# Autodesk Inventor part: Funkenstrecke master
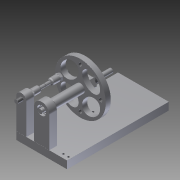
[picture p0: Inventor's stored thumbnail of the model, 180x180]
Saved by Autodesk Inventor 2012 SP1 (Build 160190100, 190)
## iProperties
Created: 2012-10
Part Number: Funkenstrecke master
Material: Default
Document SubType Name: Modeling
Designer: Dominic Mähling
Density: 1 g/cm^3
Author: Dominic Mähling
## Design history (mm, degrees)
sketch "Skizze1"
  geometry: L1 (100, -200)-(-100, -200); L2 (-100, -200)-(-100, 200); L3 (-100, 200)-(100, 200); L4 (100, 200)-(100, -200); 3 further points
  constraints: 8 end point, 2 midpoint, 2 parallel, 1 horizontal, 1 horizontal alignment, 1 perpendicular, 1 vertical alignment
  dimensions: "d0" = 200 distance of L2.end L3.end; "d1" = 400 distance of L1.end L2.end
extrude "Extrusion1" new body sketch "Skizze1" distance "d2" = 30; taper "d3" = 0 deg
sketch "Skizze3"
  geometry: L1 (200, 30)-(0, 30) reference; L2 (0, 30)-(0, 150); L3 (40, 30)-(40, 150); L4 (70, 30)-(70, 150); L5 (130, 30)-(130, 150); A1 r 20 centre (20, 150) between (40, 150) and (0, 150); A2 r 30 centre (100, 150) between (130, 150) and (70, 150); 2 further points
  constraints: 8 end point, 4 point on circle, 4 tangent, 3 parallel, 3 point on line, 2 centre point, 1 horizontal alignment, 1 midpoint, 1 perpendicular, 1 vertical alignment
  dimensions: "d4" = 120 distance of L1.end L2.end; "d6" = 40 distance between parallel lines of L2 L3; "d7" = 60 distance between parallel lines of L5 L4
extrude "Extrusion2" new body sketch "Skizze3" distance "d8" = 30; taper "d9" = 0 deg
extrude "Extrusion3" new body sketch "Skizze3" distance "d10" = 30; taper "d11" = 0 deg
sketch "Skizze4"
  geometry: A1 r 30 centre (100, 150) between (130, 150) and (70, 150) reference; 2 further points
  constraints: 1 coincident
hole "Bohrung1" sketch "Skizze4" at (100, 150) diameter "d12" = 30; stored, may be unused: countersink angle "d16" = 90 deg, drill point angle "d18" = 118 deg; dims "d13" = 6, "d14" = 35, "d15" = 10, "d17" = 8
sketch "Skizze5"
  geometry: A1 r 20 centre (20, 150) between (40, 150) and (0, 150) reference; 2 further points
  constraints: 1 coincident
hole "Bohrung2" sketch "Skizze5" at (20, 150) diameter "d19" = 13.835; stored, may be unused: countersink angle "d23" = 90 deg, drill point angle "d25" = 118 deg; dims "d20" = 30, "d21" = 42, "d22" = 12, "d24" = 8
workplane "Arbeitsebene1"
sketch "Skizze7"
  geometry: L1 (-20, 0)-(-20, 30) reference; L2 (-20, 30)-(-6.918, 30) reference; L3 (-6.918, 30)-(-6.918, 0) reference; L4 (-6.918, 0)-(-20, 0) reference; L5 (120, 30)-(120, 0) reference; L6 (120, 0)-(6.918, 0) reference; L7 (6.918, 0)-(6.918, 30) reference; L8 (6.918, 30)-(120, 30) reference; L9 (0, -20)-(-8, -20); L10 (-6.918, 0)-(6.918, 0); L11 (-8, -20)-(-8, 30); L12 (-8, 30)-(-12, 30); L13 (-12, 30)-(-12, 64); L14 (0, -20)-(0, 40); L15 (0, 40)-(-6, 40); L16 (-6, 40)-(-6, 70); L17 (0, 40)-(-5.95, 40); L18 (-5.95, 40)-(-5.95, 90); L19 (-5.95, 90)-(0, 90); L20 (0, 90)-(0, 40); L21 (-6, 70)-(-4.183, 70); L22 (150, 0)-(120, 0) reference; L23 (120, 0)-(120, 400) reference; L24 (120, 400)-(150, 400) reference; L25 (150, 400)-(150, 0) reference; A1 r 6 centre (-6, 64) between (-6, 70) and (-12, 64); 2 further points
  constraints: 26 end point, 5 perpendicular, 3 parallel, 2 horizontal, 2 point on circle, 2 point on line, 2 tangent, 1 centre point, 1 horizontal alignment, 1 midpoint, 1 vertical alignment
  dimensions: "d43" = 20 distance between parallel lines of L4 L9; "d44" = 12 distance between parallel lines of L14 L13; "d45" = 6 distance between parallel lines of L14 L16; "d46" = 10 distance between parallel lines of L8 L15; "d47" = 8 distance between parallel lines of L14 L11; "d48" = 5.95 distance of L18.end L19.end; "d49" = 50 distance of L17.end L18.end; "d51" = 40 distance from line of L16.end L12
  node "Schnittkanten projizieren2"
revolve "Umdrehung2" stored, may be unused: angle "d42" = 90 deg
revolve "Umdrehung3" stored, may be unused: angle "d50" = 90 deg
feature "Gewinde1" dims "d52" = 10, "d53" = 0
sketch "Skizze6"
  geometry: L1 (-200, 0)-(-200, 30) reference; L2 (-200, 30)-(200, 30) reference; L3 (200, 30)-(200, 0) reference; L4 (200, 0)-(-200, 0) reference; L5 (-200, 180)-(-170, 180) reference; L6 (-170, 180)-(-170, 165) reference; L7 (-170, 165)-(-190, 165) reference; L8 (-190, 165)-(-190, 167.5) reference; L9 (-190, 167.5)-(-200, 167.5) reference; L10 (-200, 167.5)-(-200, 180) reference; L11 (-170, 30)-(-200, 30) reference; L12 (-200, 30)-(-200, 132.5) reference; L13 (-200, 132.5)-(-190, 132.5) reference; L14 (-190, 132.5)-(-190, 135) reference; L15 (-190, 135)-(-170, 135) reference; L16 (-170, 135)-(-170, 30) reference; L17 (-201, 158.5)-(-206, 158.5); L18 (-206, 158.5)-(-206, 150); L19 (-206, 150)-(73, 150); L20 (73, 150)-(73, 158.5); L21 (73, 158.5)-(33, 158.5); L22 (33, 158.5)-(33, 157.5); L23 (33, 157.5)-(32, 157.5); L24 (32, 157.5)-(32, 158.5); L25 (32, 158.5)-(22, 158.5); L26 (22, 158.5)-(22, 162); L27 (22, 162)-(-48, 162); L28 (-48, 162)-(-48, 167.5); L29 (-48, 167.5)-(-160, 167.5); L30 (-160, 167.5)-(-160, 162); L31 (-190, 162)-(-190, 158.5); L32 (-190, 158.5)-(-200, 158.5); L33 (-200, 158.5)-(-200, 157.5); L34 (-200, 157.5)-(-201, 157.5); L35 (-201, 157.5)-(-201, 158.5); L36 (-170, 165)-(-170, 135); L37 (-110, 144.05)-(-110, 155.95) reference; L38 (-48, 150)-(-48, 250); L39 (-48, 250)-(-28, 250); L40 (-28, 250)-(-28, 150); L41 (-190, 162)-(-160, 162); 2 further points
  constraints: 48 end point, 13 parallel, 10 perpendicular, 6 horizontal alignment, 3 vertical alignment, 2 point on line, 1 midpoint
  dimensions: "d27" = 8.5 distance of L17.end L18.end; "d28" = 1 distance between parallel lines of L17 L34; "d29" = 1 distance of L33.end L34.end; "d30" = 5 distance of L17.start L17.end; "d32" = 1 distance of L22.end L23.end (= d29); "d33" = 40 distance of L20.end L21.end; "d54" = 60 distance between parallel lines of L36 L37 (derived); "d55" = 20 distance of L38.end L39.end; "d56" = 100 distance between parallel lines of L19 L39; "d57" = 122 distance between parallel lines of L36 L38 (computed from d54); "d59" = 10 distance of L24.end L25.end (= d60); "d60" = 10 distance of L8.end L9.end (derived); "d125" = 30 distance of L5.start L5.end (derived); "d166" = 60 distance between parallel lines of L24 L40 (computed from d125); "d220" = 10 distance between parallel lines of L30 L36; "d221" = 12 distance between parallel lines of L19 L41; "d222" = 17.5 distance between parallel lines of L19 L29
  node "Schnittkanten projizieren1"
revolve "Umdrehung1" stored, may be unused: angle "d26" = 90 deg
revolve "Umdrehung4" stored, may be unused: angle "d61" = 90 deg
sketch "Skizze26"
  geometry: C1 r 8 at (-80, 0) reference; 2 further points
  constraints: 1 coincident
hole "Bohrung15" sketch "Skizze26" at (-80, 0) diameter "d197" = 13.835; stored, may be unused: countersink angle "d201" = 90 deg, drill point angle "d203" = 118 deg; dims "d198" = 30, "d199" = 4, "d200" = 2, "d202" = 8
pattern_circular "Runde Anordnung4" dims angle "d205" = 360 deg
sketch "Skizze21"
  geometry: L1 (25.981, 0)-(12.99, -22.5); L2 (12.99, -22.5)-(-12.99, -22.5); L3 (-12.99, -22.5)-(-25.981, 0); L4 (-25.981, 0)-(-12.99, 22.5); L5 (-12.99, 22.5)-(12.99, 22.5); L6 (12.99, 22.5)-(25.981, 0); C1 r 100 at (0, 0) reference; 2 further points
  constraints: 12 end point, 1 coincident, 1 horizontal alignment, 13 other
  dimensions: "d167" = 45 distance between parallel lines of L2 L5
extrude "Extrusion6" new body sketch "Skizze21" distance "d168" = 20; taper "d169" = 0 deg
sketch "Skizze12" dims "d108" = 40, "d109" = 30
  geometry: L1 (0, 0)-(-42.426, 42.426); L2 (0, 0)-(28.671, 0); C1 r 100 at (0, 0) reference; 2 further points; 1 other entity
  constraints: 4 end point, 1 coincident, 1 horizontal, 3 other
  dimensions: "d106" = 60 distance of L1.start L1.end; "d207" = 45 deg angle of L1 L2
extrude "Extrusion5" cut sketch "Skizze12" stored distance "d110" = 20; taper "d111" = 0 deg
pattern_circular "Runde Anordnung2" dims angle "d113" = 360 deg
feature "Gewinde3" dims "d177" = 10, "d178" = 0
sketch "Skizze23"
  geometry: C1 r 100 at (0, 0) reference; 2 further points
  constraints: 1 coincident
hole "Bohrung12" sketch "Skizze23" at (0, 0) diameter "d170" = 20.752; stored, may be unused: countersink angle "d174" = 90 deg, drill point angle "d176" = 118 deg; dims "d171" = 30, "d172" = 4, "d173" = 2, "d175" = 8
sketch "Skizze24"
  geometry: C1 r 100 at (0, 0) reference; 2 further points
  constraints: 1 coincident
hole "Bohrung13" sketch "Skizze24" at (0, 0) diameter "d179" = 20.752; stored, may be unused: countersink angle "d183" = 90 deg, drill point angle "d185" = 118 deg; dims "d180" = 30, "d181" = 4, "d182" = 2, "d184" = 8
sketch "Skizze25"
  geometry: L1 (25.981, 20)-(0, 20) reference; L2 (0, 0)-(0, 20) reference; L3 (25.981, 0)-(0, 0) reference; L4 (25.981, 0)-(25.981, 20) reference; 4 further points
  constraints: 2 midpoint, 1 horizontal alignment, 1 vertical alignment
hole "Bohrung14" sketch "Skizze25" at (12.99, 10) diameter "d186" = 4.917; stored, may be unused: countersink angle "d190" = 90 deg, drill point angle "d192" = 118 deg; dims "d187" = 30, "d188" = 4, "d189" = 2, "d191" = 8
pattern_circular "Runde Anordnung3" dims angle "d194" = 360 deg
workplane "Arbeitsebene6"
sketch "Skizze28"
  geometry: L1 (23, -6)-(23, 6) reference; 3 further points
  constraints: 1 horizontal alignment, 1 midpoint
  dimensions: "d210" = 10 distance from line of L1 point (13, 0)
hole "Bohrung16" sketch "Skizze28" at (13, 0) diameter "d211" = 4.917; stored, may be unused: countersink angle "d215" = 90 deg, drill point angle "d217" = 118 deg; dims "d212" = 30, "d213" = 4, "d214" = 2, "d216" = 8
sketch "Skizze14"
  geometry: L1 (40, 30)-(0, 30) reference; L2 (0, 0)-(0, 30) reference; L3 (40, 0)-(0, 0) reference; L4 (40, 0)-(40, 30) reference; L5 (10, 15)-(30, 15); 6 further points
  constraints: 3 midpoint, 2 coincident, 2 end point, 1 horizontal alignment, 1 perpendicular, 1 vertical alignment
  dimensions: "d126" = 20 distance of L5.start L5.end (= 0.5 x d135); "d135" = 40 distance of L1.start L1.end (derived)
hole "Bohrung7" sketch "Skizze14" at (10, 15), (30, 15) diameter "d128" = 6.647; stored, may be unused: countersink angle "d132" = 90 deg, drill point angle "d134" = 118 deg; dims "d129" = 12, "d130" = 42, "d131" = 12, "d133" = 15
sketch "Skizze15"
  geometry: L1 (15, 15)-(45, 15); L2 (60, 30)-(0, 30) reference; L3 (0, 0)-(0, 30) reference; L4 (60, 0)-(0, 0) reference; L5 (60, 0)-(60, 30) reference; 6 further points
  constraints: 3 midpoint, 2 coincident, 2 end point, 1 horizontal, 1 horizontal alignment, 1 vertical alignment
  dimensions: "d136" = 60 distance of L4.start L3.start (derived); "d137" = 30 distance of L1.start L1.end (= 0.5 x d136)
hole "Bohrung8" sketch "Skizze15" at (15, 15), (45, 15) diameter "d138" = 6.647; stored, may be unused: countersink angle "d142" = 90 deg, drill point angle "d144" = 118 deg; dims "d139" = 12, "d140" = 42, "d141" = 12, "d143" = 15
sketch "Skizze17"
  geometry: C1 r 3.324 at (90, -185) reference; C2 r 3.324 at (70, -185) reference; 3 further points
  constraints: 2 coincident
hole "Bohrung9" sketch "Skizze17" at (70, -185), (90, -185) diameter "d145" = 8.1; stored, may be unused: countersink angle "d149" = 90 deg, drill point angle "d151" = 118 deg; dims "d146" = 12, "d147" = 14, "d148" = 10, "d150" = 15
mirror "Spiegeln1"
workplane "Arbeitsebene3"
sketch "Skizze19"
  geometry: C1 r 3.324 at (15, -185) reference; C2 r 3.324 at (-15, -185) reference; 1 further point
hole "Bohrung10" sketch "Skizze19" at (-15, -185), (15, -185) diameter "d152" = 8.1; stored, may be unused: countersink angle "d156" = 90 deg, drill point angle "d158" = 118 deg; dims "d153" = 12, "d154" = 14, "d155" = 10, "d157" = 15
mirror "Spiegeln2"
workplane "Arbeitsebene4"
sketch "Skizze27"
  geometry: L1 (12, 6.928)-(12, -6.928); L2 (12, -6.928)-(0, -13.856); L3 (0, -13.856)-(-12, -6.928); L4 (-12, -6.928)-(-12, 6.928); L5 (-12, 6.928)-(0, 13.856); L6 (0, 13.856)-(12, 6.928); C1 r 12 at (0, 0) reference; 3 further points
  constraints: 12 end point, 1 coincident, 1 horizontal alignment, 1 midpoint, 1 tangent, 13 other
extrude "Extrusion7" join sketch "Skizze27" distance "d208" = 10; taper "d209" = 0 deg
mirror "Spiegeln3"
mirror "Spiegeln4"
workplane "Arbeitsebene5"
feature "Trennen1"
fillet "Rundung2" dims "d223" = 0.2, "d224" = 0.2
node "Bodenplatte"
node "Elektrodenhalterung"
node "Lagerhalterung"
node "Welle"
node "Elektrodeneinsatz"
node "Elektrode"
node "Scheibe"
node "Projizierte Kontur3"
node "Projizierte Kontur4"
node "Projizierte Kontur5"
node "Mutter"
node "Projizierte Kontur7"
feature "Anordnung von Elektrodeneinsatz:1"
node "Elektrodeneinsatz rot"
feature "Anordnung von Elektrode:2"
node "Elektrode rot"
other parameters: "d31" = 11
